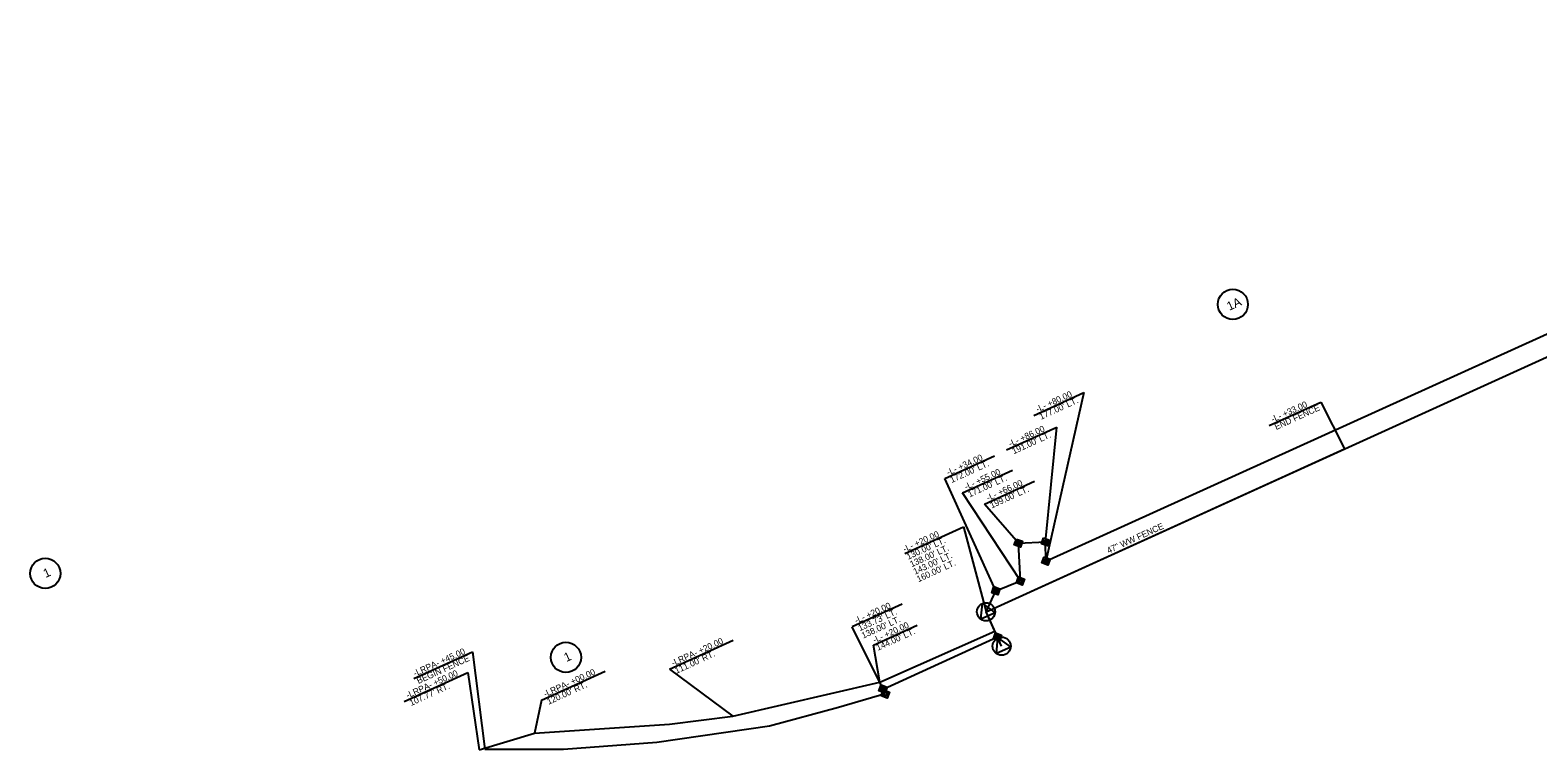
# Model space of a CAD drawing. Extents: x 2242607 to 2250377, y 661355 to 663917.
# Drawn here: x 2247876 to 2249075, y 663287 to 663859 of the extents above; entities that cross this region are included whole.
import ezdxf

# ---------------------------------------------------------------- set-up
doc = ezdxf.new("R2010")
doc.units = 0
for name, color, linetype in [('Prop Easement Construction', 7, 'Continuous'), ('Prop Easement Construction Station Offsets', 7, 'Continuous'), ('Prop Easement Permanent Drainage', 7, 'Continuous'), ('Prop Easement Permanent Drainage Station Offsets', 7, 'Continuous'), ('Prop Easement Permanent Utility', 7, 'Continuous'), ('Prop Easement Permanent Utility Station Offsets', 7, 'Continuous'), ('Prop Fence Woven Wire', 7, 'Continuous'), ('Prop Parcel Number CELL', 7, 'Continuous'), ('Prop ROW CA Lines', 7, 'Continuous'), ('Prop ROW Marker CELL', 7, 'Continuous'), ('Prop ROW Permanent Easement CELL', 7, 'Continuous'), ('Prop ROW RW CA Lines', 7, 'Continuous'), ('Prop ROW Station Offsets', 7, 'Continuous')]:
    doc.layers.add(name, color=color, linetype=linetype)

msp = doc.modelspace()

# ---------------------------------------------------------------- linework, layer by layer
at = {"layer": 'Prop Easement Construction'}
for p, q in [((2248552, 663340.7), (2248643.5, 663381.1)), ((2248435, 663313.6), (2248552, 663340.7)), ((2248277.2, 663300.1), (2248384.6, 663307.2)), ((2248384.6, 663307.2), (2248435, 663313.6)), ((2248233.4, 663286.9), (2248277.2, 663300.1))]:
    msp.add_line(p, q, dxfattribs=at)
at = {"layer": 'Prop Easement Construction Station Offsets'}
for p, q in [((2248547, 663370.2), (2248581.5, 663385.9)), ((2248384.6, 663350.9), (2248435.4, 663374.1)), ((2248552, 663340.7), (2248547, 663370.2)), ((2248173.6, 663325.3), (2248224.4, 663348.4)), ((2248224.4, 663348.4), (2248233.4, 663286.9)), ((2248282.9, 663326.3), (2248333.6, 663349.4)), ((2248384.6, 663350.9), (2248435, 663313.6)), ((2248282.9, 663326.3), (2248277.2, 663300.1))]:
    msp.add_line(p, q, dxfattribs=at)
at = {"layer": 'Prop Easement Permanent Drainage'}
for p, q in [((2248554.5, 663335.2), (2248645.5, 663376.6)), ((2248556.3, 663331.3), (2248554.5, 663335.2))]:
    msp.add_line(p, q, dxfattribs=at)
at = {"layer": 'Prop Easement Permanent Drainage Station Offsets'}
for p in [(2248569.8, 663402.7), (2248554.5, 663335.2)]:
    msp.add_line(p, (2248530, 663384.6), dxfattribs=at)
at = {"layer": 'Prop Easement Permanent Utility'}
for p, q in [((2248684, 663436.9), (2249613.1, 663857.9)), ((2248662.2, 663451.2), (2248683.7, 663452.1)), ((2248663.8, 663421.1), (2248662.2, 663451.2)), ((2248684, 663436.9), (2248683.7, 663452.1)), ((2248636.4, 663396.6), (2248644.2, 663413.3)), ((2248644.2, 663413.3), (2248663.8, 663421.1))]:
    msp.add_line(p, q, dxfattribs=at)
at = {"layer": 'Prop Easement Permanent Utility Station Offsets'}
for p, q in [((2248674.5, 663552.7), (2248714.3, 663570.8)), ((2248714.3, 663570.8), (2248684, 663436.9)), ((2248652.8, 663525.2), (2248692.6, 663543.4)), ((2248683.7, 663452.1), (2248692.6, 663543.4)), ((2248603.5, 663502.5), (2248643.2, 663520.6)), ((2248617.7, 663491), (2248657.5, 663509.1)), ((2248644.2, 663413.3), (2248603.5, 663502.5)), ((2248635.2, 663482.2), (2248675, 663500.3)), ((2248663.8, 663421.1), (2248617.7, 663491)), ((2248662.2, 663451.2), (2248635.2, 663482.2))]:
    msp.add_line(p, q, dxfattribs=at)
at = {"layer": 'Prop Fence Woven Wire'}
for p, q in [((2248636.4, 663396.6), (2248921.4, 663526.1)), ((2248645.5, 663376.6), (2248636.4, 663396.6)), ((2248554.5, 663335.2), (2248645.5, 663376.6)), ((2248519, 663320.7), (2248556.1, 663331.7)), ((2248556.1, 663331.7), (2248554.5, 663335.2)), ((2248464.2, 663306.1), (2248519, 663320.7)), ((2248374.6, 663293), (2248464.2, 663306.1)), ((2248300.4, 663287.4), (2248374.6, 663293)), ((2248237.9, 663287.4), (2248300.4, 663287.4))]:
    msp.add_line(p, q, dxfattribs=at)
at = {"layer": 'Prop Parcel Number CELL'}
for p, q in [((2248832.7, 663640.9), (2248832.7, 663640.9)), ((2247888.2, 663427.1), (2247888.2, 663427.1)), ((2248302.3, 663360.4), (2248302.3, 663360.4))]:
    msp.add_line(p, q, dxfattribs=at)
for centre in [(2248832.7, 663640.9), (2247888.2, 663427.1), (2248302.3, 663360.4)]:
    msp.add_circle(centre, 12, dxfattribs=at)
at = {"layer": 'Prop ROW CA Lines'}
msp.add_line((2248648.8, 663369.3), (2248636.4, 663396.6), dxfattribs=at)
at = {"layer": 'Prop ROW Marker CELL'}
for p, q in [((2248662.2, 663451.2), (2248662.2, 663451.2)), ((2248683.7, 663452.1), (2248683.7, 663452.1)), ((2248684, 663436.9), (2248684, 663436.9)), ((2248644.2, 663413.3), (2248644.2, 663413.3)), ((2248663.8, 663421.1), (2248663.8, 663421.1)), ((2248636.4, 663396.6), (2248636.4, 663396.6)), ((2248645.5, 663376.6), (2248645.5, 663376.6)), ((2248648.8, 663369.3), (2248648.8, 663369.3)), ((2248554.5, 663335.2), (2248554.5, 663335.2)), ((2248556.3, 663331.3), (2248556.3, 663331.3))]:
    msp.add_line(p, q, dxfattribs=at)
for points in [[(2248632.2, 663390.8), (2248633.5, 663403.2), (2248643.6, 663395.9)], [(2248644.7, 663363.4), (2248645.9, 663375.9), (2248656, 663368.6)]]:
    msp.add_lwpolyline(points, close=True, dxfattribs=at)
for centre in [(2248636.4, 663396.6), (2248648.8, 663369.3)]:
    msp.add_circle(centre, 7.2, dxfattribs=at)
at = {"layer": 'Prop ROW Permanent Easement CELL'}
for points in [[(2248660.7, 663454.4), (2248665.5, 663452.6), (2248663.7, 663447.9), (2248658.9, 663449.7)], [(2248661.4, 663452.8), (2248663.8, 663451.9), (2248662.9, 663449.5), (2248660.6, 663450.4)], [(2248682.2, 663455.4), (2248687, 663453.6), (2248685.2, 663448.9), (2248680.4, 663450.6)], [(2248683, 663453.8), (2248685.3, 663452.9), (2248684.5, 663450.5), (2248682.1, 663451.4)], [(2248682.5, 663440.2), (2248687.3, 663438.4), (2248685.5, 663433.6), (2248680.8, 663435.4)], [(2248683.3, 663438.6), (2248685.7, 663437.7), (2248684.8, 663435.3), (2248682.4, 663436.2)], [(2248662.3, 663424.4), (2248667, 663422.6), (2248665.2, 663417.8), (2248660.5, 663419.6)], [(2248642.7, 663416.6), (2248647.5, 663414.8), (2248645.7, 663410.1), (2248640.9, 663411.8)], [(2248643.5, 663415), (2248645.9, 663414.1), (2248645, 663411.7), (2248642.6, 663412.6)], [(2248663, 663422.7), (2248665.4, 663421.9), (2248664.5, 663419.5), (2248662.1, 663420.4)], [(2248644, 663379.9), (2248648.8, 663378.1), (2248647, 663373.3), (2248642.3, 663375.1)], [(2248644.8, 663378.2), (2248647.2, 663377.3), (2248646.3, 663375), (2248643.9, 663375.8)], [(2248553, 663338.5), (2248557.8, 663336.7), (2248556, 663332), (2248551.2, 663333.7)], [(2248553.7, 663336.9), (2248556.1, 663336), (2248555.2, 663333.6), (2248552.9, 663334.5)], [(2248554.8, 663334.6), (2248559.5, 663332.8), (2248557.8, 663328.1), (2248553, 663329.9)], [(2248555.5, 663333), (2248557.9, 663332.1), (2248557, 663329.7), (2248554.6, 663330.6)]]:
    msp.add_lwpolyline(points, close=True, dxfattribs=at)
at = {"layer": 'Prop ROW RW CA Lines'}
msp.add_line((2248636.4, 663396.6), (2249653.8, 663858.8), dxfattribs=at)
at = {"layer": 'Prop ROW Station Offsets'}
for p, q in [((2248861.6, 663544.6), (2248902.6, 663563.3)), ((2248902.6, 663563.3), (2248921.4, 663526.1)), ((2248571.7, 663442.8), (2248618.4, 663464.1)), ((2248618.4, 663464.1), (2248636.4, 663396.6)), ((2248181.2, 663343.5), (2248228, 663364.8)), ((2248228, 663364.8), (2248237.9, 663287.4))]:
    msp.add_line(p, q, dxfattribs=at)

# ---------------------------------------------------------------- texts
at = {"layer": 'Prop Easement Construction Station Offsets'}
for s, p in [('-L- +20.00', (2248547.7, 663371.6)), ("144.00' LT.", (2248550.4, 663365.6)), ('-LRPA- +20.00', (2248387.5, 663353.3)), ("111.00' RT.", (2248390.2, 663347.3)), ('-LRPA- +50.00', (2248176.5, 663327.7)), ('-LRPA- +00.00', (2248285.8, 663328.7)), ("120.00' RT.", (2248288.5, 663322.7)), ("107.77' RT.", (2248179.2, 663321.7))]:
    msp.add_text(s, height=5, rotation=24.4301, dxfattribs=at).set_placement(p)
at = {"layer": 'Prop Easement Permanent Drainage Station Offsets'}
for s, p in [('-L- +20.00', (2248533.3, 663387.1)), ("133.73' LT.", (2248536, 663381.1)), ("138.00' LT.", (2248538.7, 663375.2))]:
    msp.add_text(s, height=5, rotation=24.4301, dxfattribs=at).set_placement(p)
at = {"layer": 'Prop Easement Permanent Utility Station Offsets'}
for s, p in [('-L- +80.00', (2248677.4, 663555.1)), ("177.00' LT.", (2248680.1, 663549.1)), ('-L- +86.00', (2248655.7, 663527.6)), ("191.00' LT.", (2248658.4, 663521.7)), ('-L- +34.00', (2248606.4, 663504.8)), ("172.00' LT.", (2248609.1, 663498.9)), ('-L- +55.00', (2248620.6, 663493.4)), ("171.00' LT.", (2248623.3, 663487.4)), ('-L- +66.00', (2248638.1, 663484.6)), ("199.00' LT.", (2248640.9, 663478.6))]:
    msp.add_text(s, height=5, rotation=24.4301, dxfattribs=at).set_placement(p)
at = {"layer": 'Prop Fence Woven Wire'}
msp.add_text('47" WW FENCE', height=5, rotation=24.4301, dxfattribs=at).set_placement((2248733.8, 663442.7))
at = {"layer": 'Prop Parcel Number CELL'}
for s, p in [('1A', (2248829.8, 663635.7)), ('1', (2247888.5, 663423.4)), ('1', (2248302.6, 663356.6))]:
    msp.add_text(s, height=7, rotation=24.4979, dxfattribs=at).set_placement(p)
at = {"layer": 'Prop ROW Station Offsets'}
for s, p in [('-L- +33.00', (2248864.5, 663547)), ('END FENCE', (2248867.2, 663541)), ('-L- +20.00', (2248571.7, 663443.9)), ("130.00' LT.", (2248574.5, 663437.9)), ("138.00' LT.", (2248577.2, 663431.9)), ("143.00' LT.", (2248579.9, 663426)), ("160.00' LT.", (2248582.6, 663420)), ('-LRPA- +45.00', (2248182.3, 663345.1)), ('BEGIN FENCE', (2248185, 663339.2))]:
    msp.add_text(s, height=5, rotation=24.4301, dxfattribs=at).set_placement(p)

doc.saveas('drawing.dxf')
